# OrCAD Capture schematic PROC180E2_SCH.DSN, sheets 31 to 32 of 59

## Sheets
31 10. USB TYPE-C POWER: size C; title: USB TYPE-C POWER
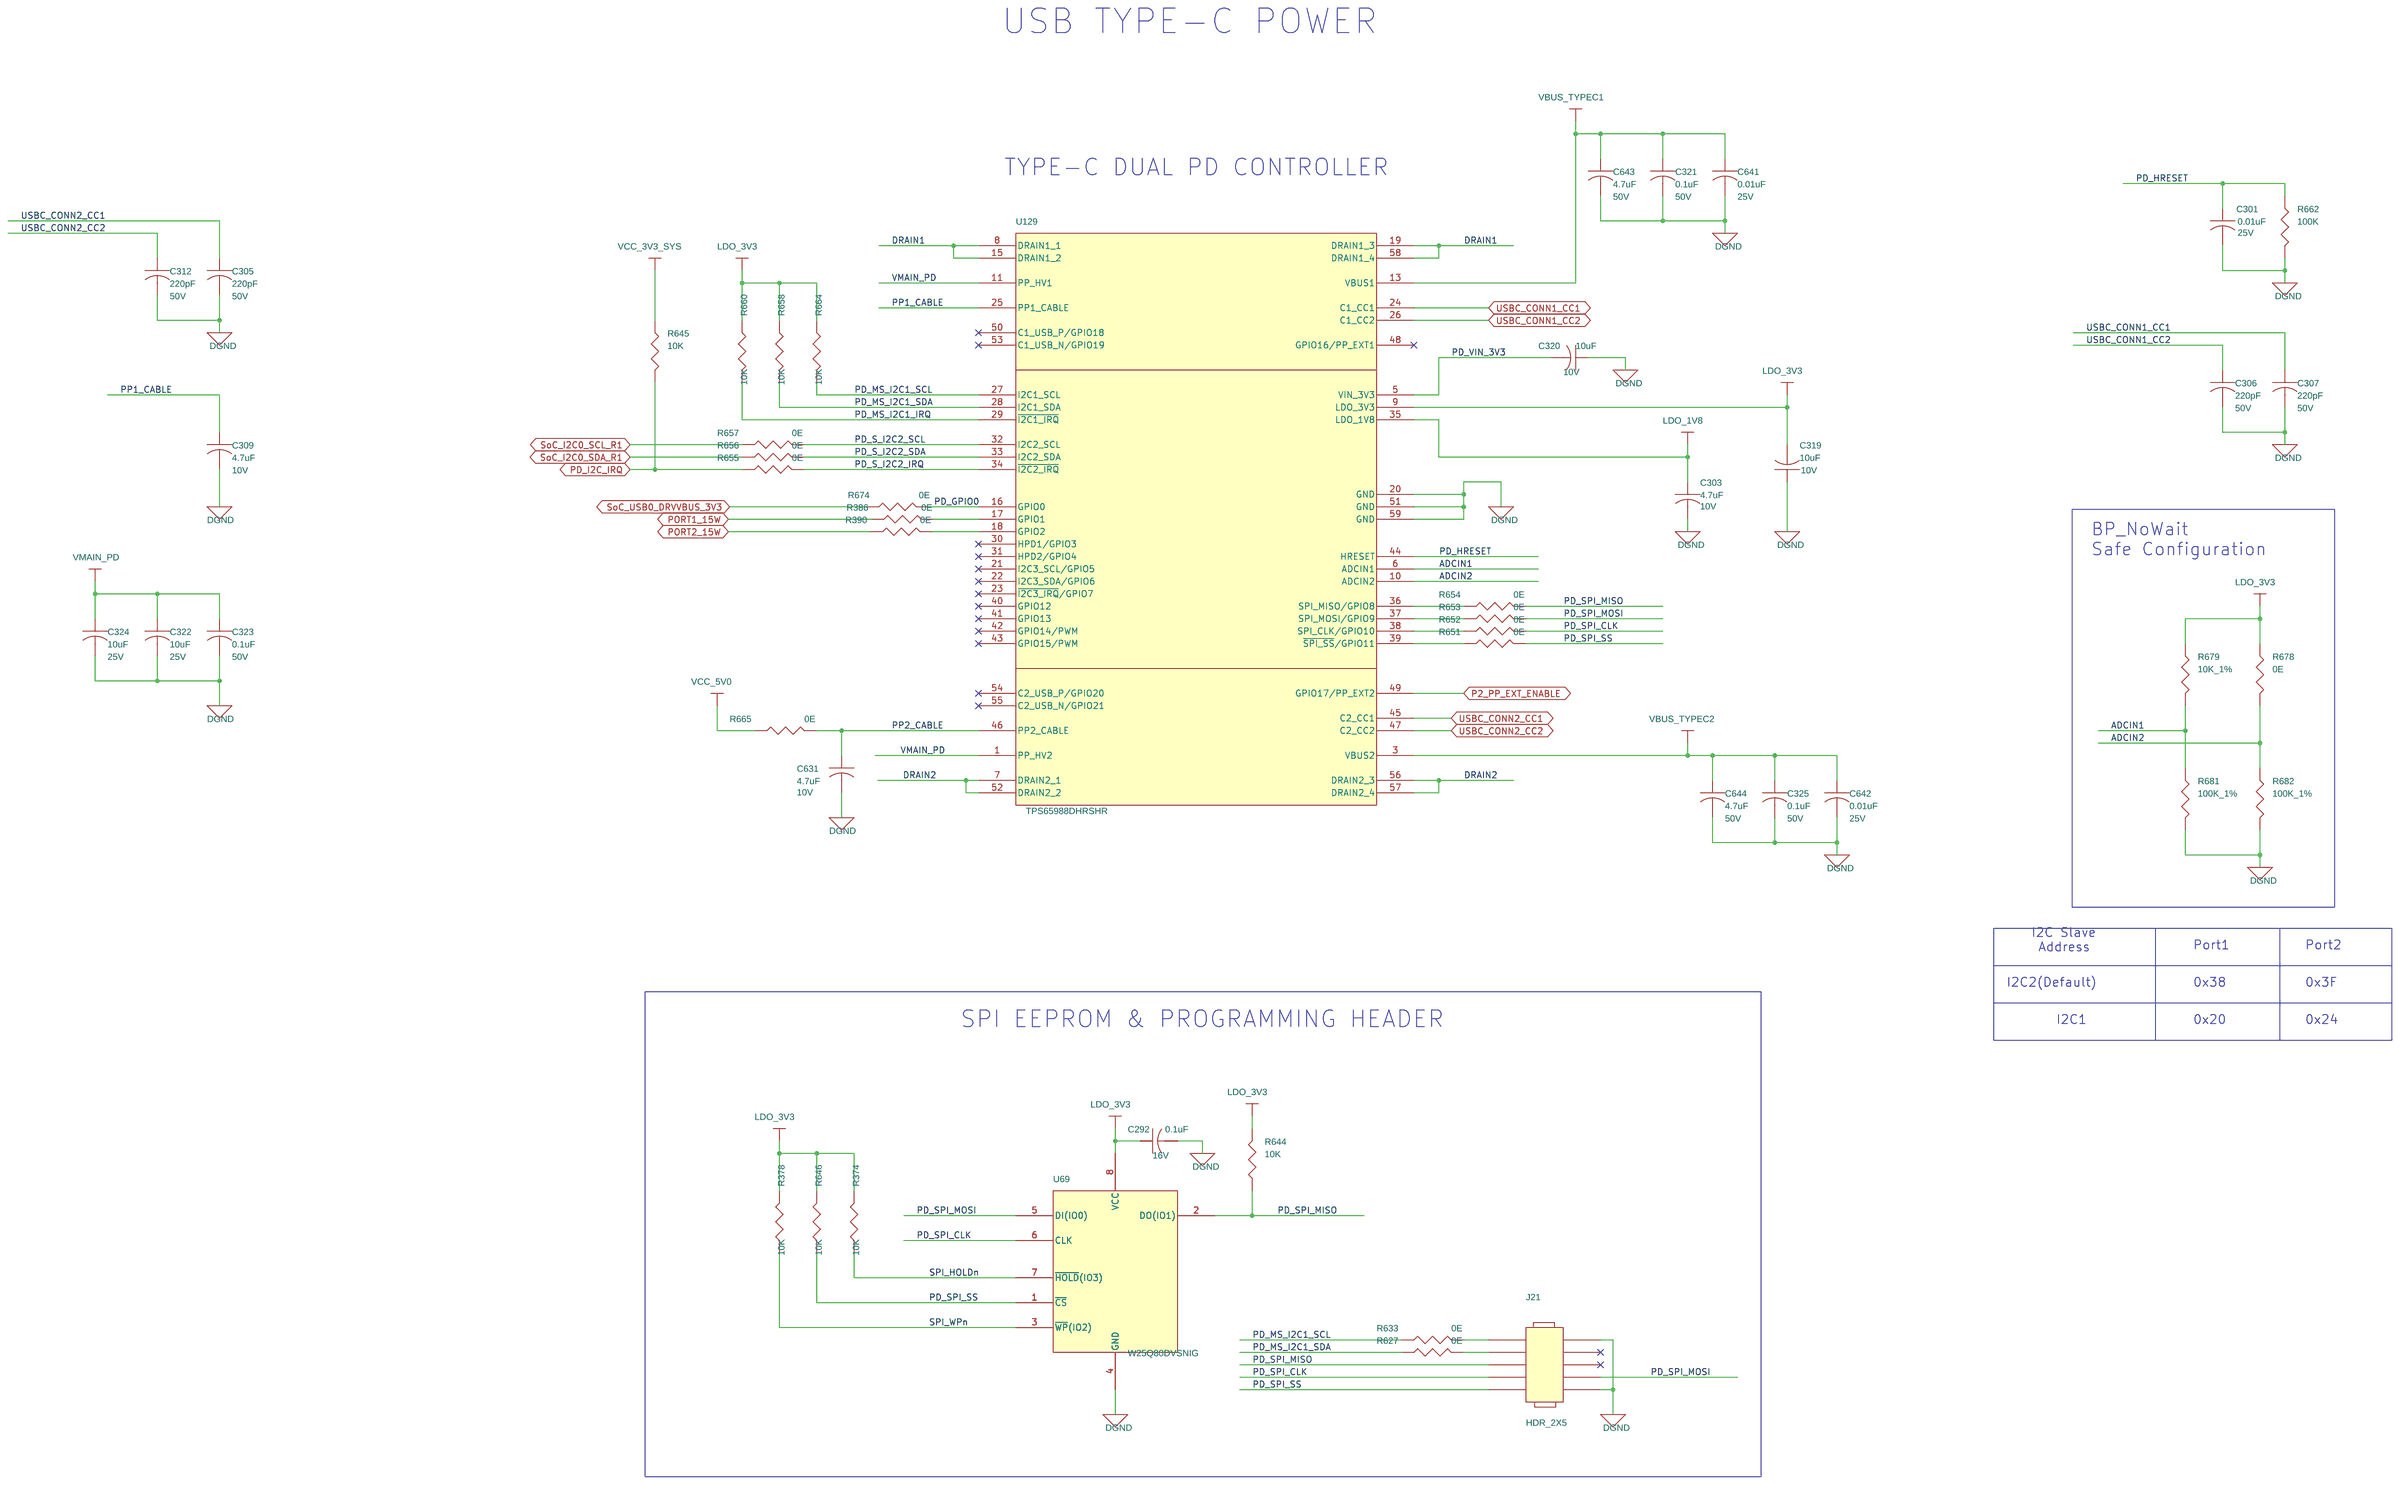
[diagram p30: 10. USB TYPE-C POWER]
32 12. PERIPHERAL POWER SUPPLY: size C; title: PERIPHERAL POWER SUPPLY
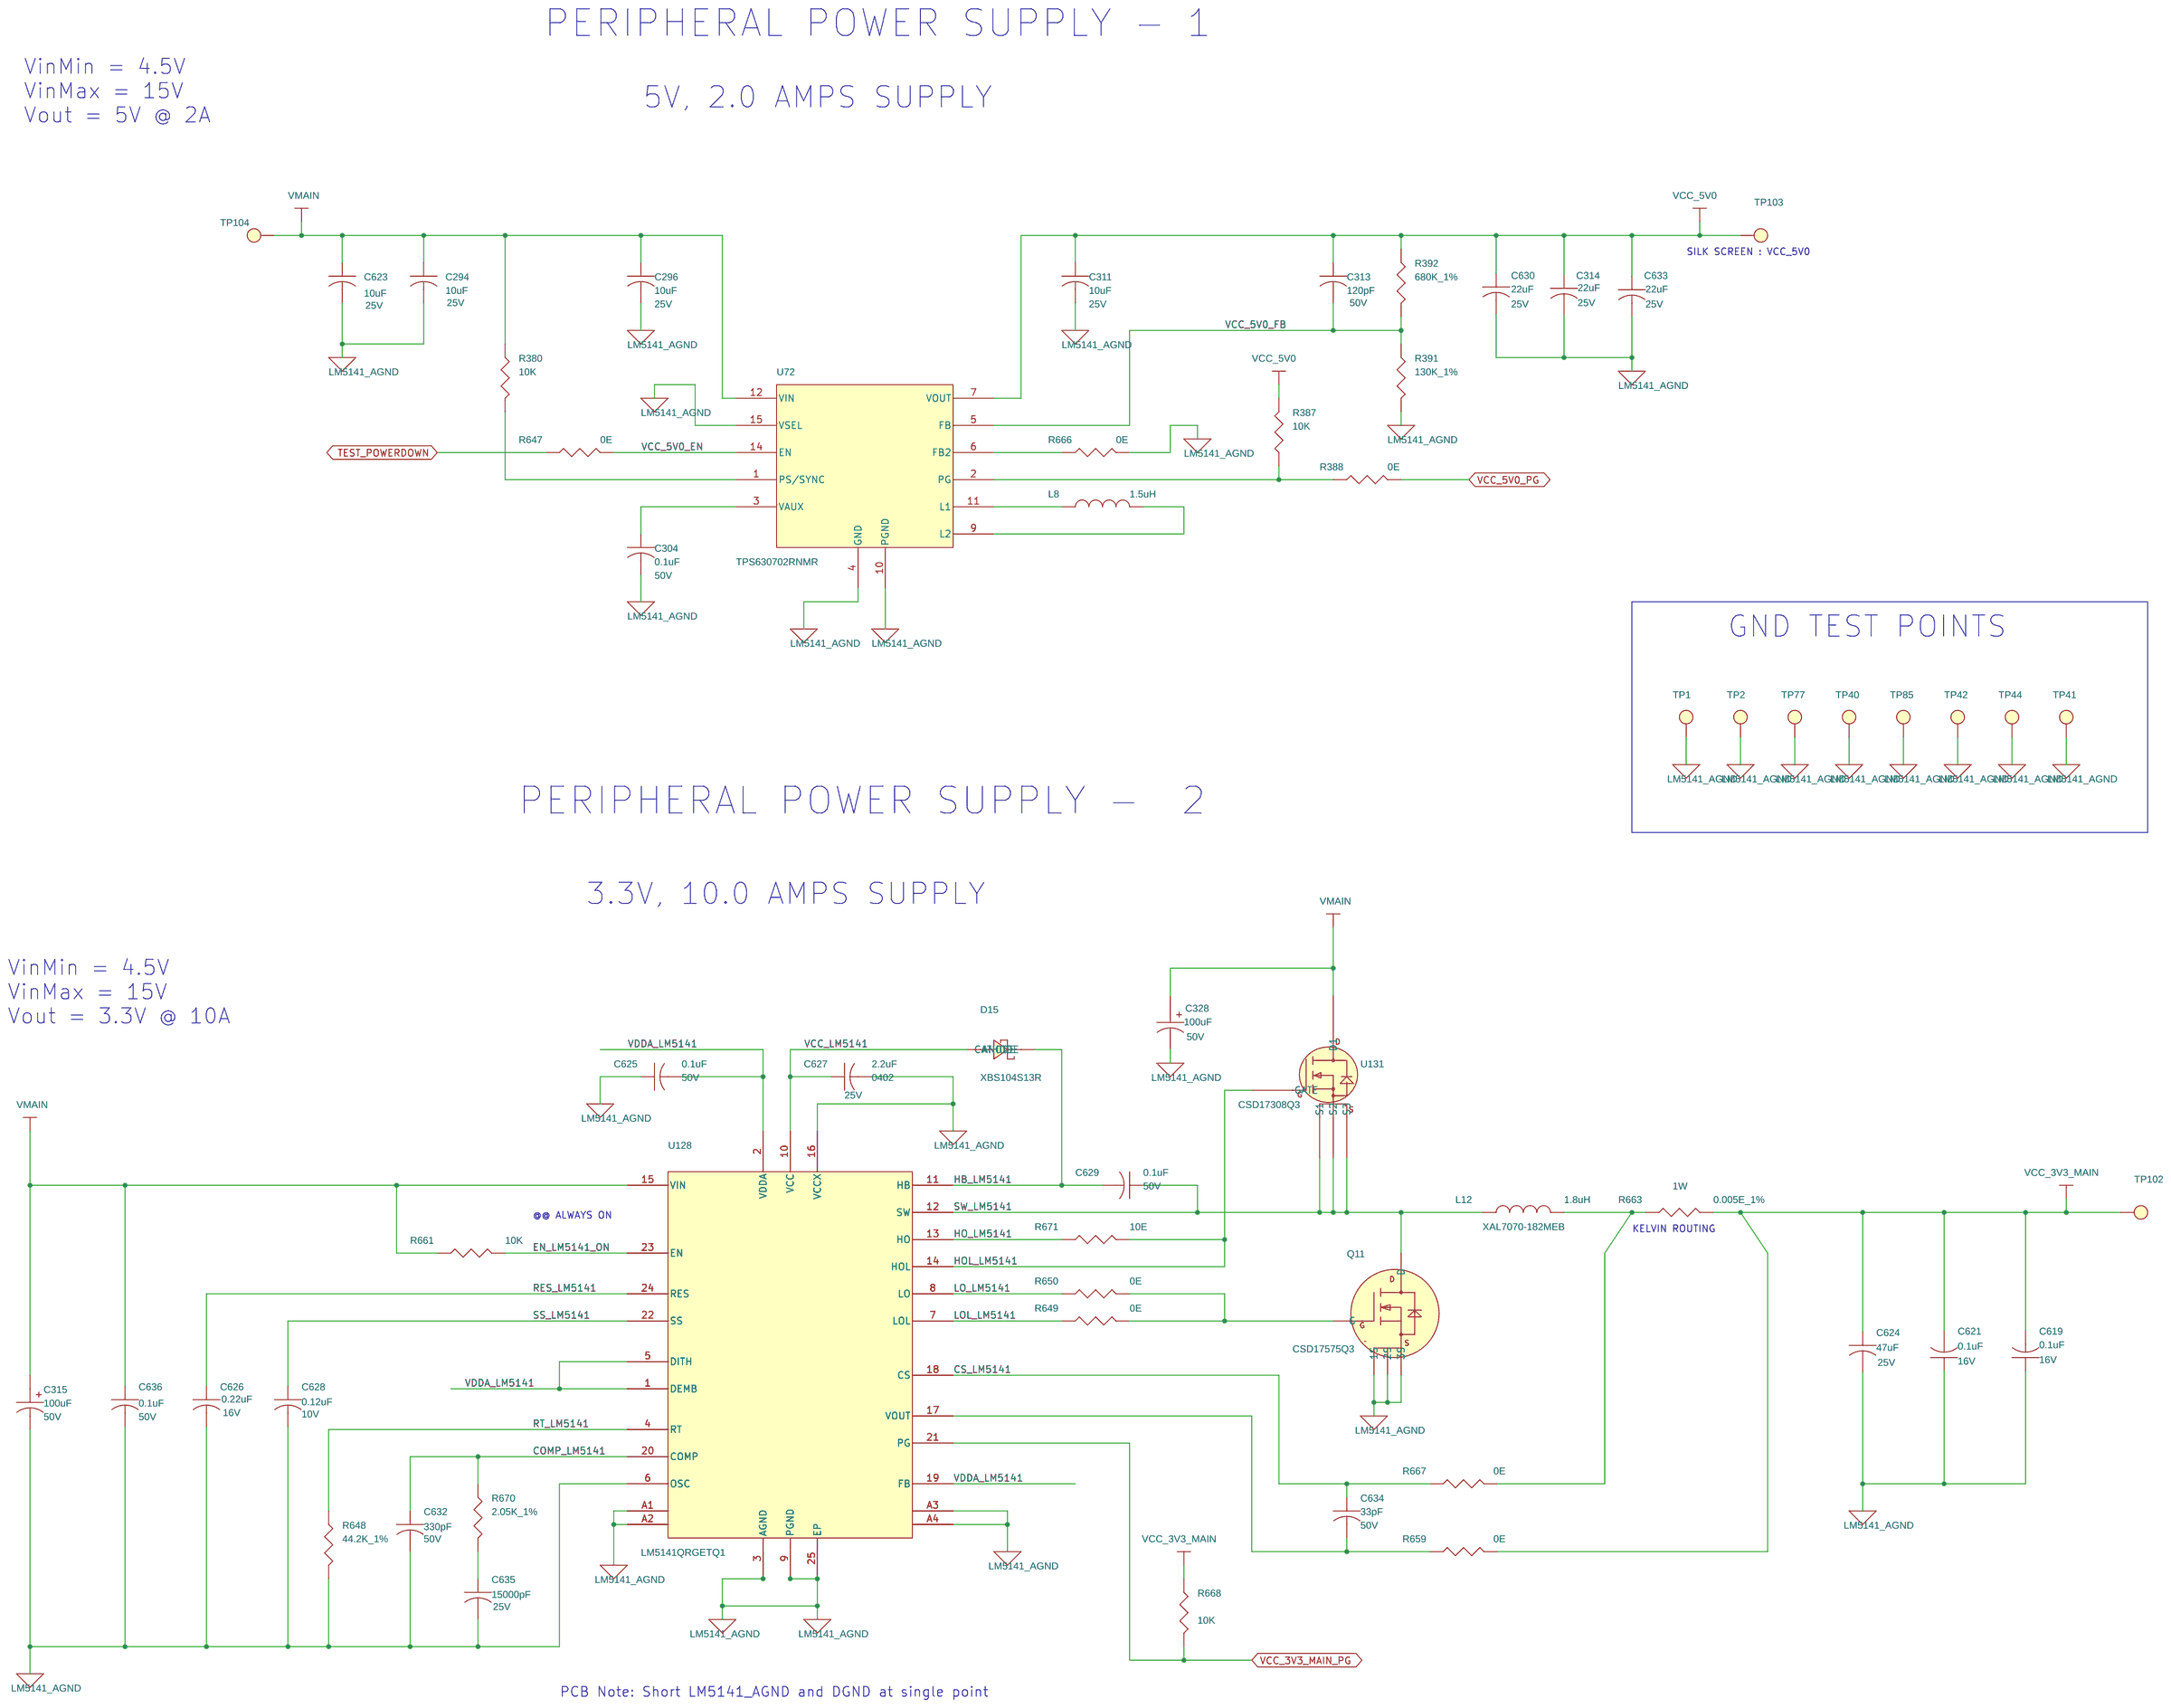
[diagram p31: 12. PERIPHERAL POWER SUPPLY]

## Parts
sheet 10. USB TYPE-C POWER
C292  0.1uF  [CAP0201_0-5]
C301  0.01uF  [CAP0201_0-5]
C303  4.7uF  [CAP0402_0-75]
C305  220pF  [CAP0402_0-75]
C306  220pF  [CAP0402_0-75]
C307  220pF  [CAP0402_0-75]
C309  4.7uF  [CAP0402_0-75]
C312  220pF  [CAP0402_0-75]
C319  10uF  [CAP0402_0-75]
C320  10uF  [CAP0402_0-75]
C321  0.1uF  [CAP0402_0-75]
C322  10uF  [CAP0603_1]
C323  0.1uF  [CAP0402_0-75]
C324  10uF  [CAP0603_1]
C325  0.1uF  [CAP0402_0-75]
C631  4.7uF  [CAP0402_0-75]
C641  0.01uF  [CAP0201_0-5]
C642  0.01uF  [CAP0201_0-5]
C643  4.7uF  [CAP0805_1-5]
C644  4.7uF  [CAP0805_1-5]
J21  HDR_2X5  [HDR_2X5_PEC05DAAN_S_T_8-6]
R374  10K  [RES0201_0-5]
R378  10K  [RES0201_0-5]
R386  0E  [RES0201_0-5]
R390  0E  [RES0201_0-5]
R627  0E  [RES0201_0-5]
R633  0E  [RES0201_0-5]
R644  10K  [RES0201_0-5]
R645  10K  [RES0201_0-5]
R646  10K  [RES0201_0-5]
R651  0E  [RES0201_0-5]
R652  0E  [RES0201_0-5]
R653  0E  [RES0201_0-5]
R654  0E  [RES0201_0-5]
R655  0E  [RES0201_0-5]
R656  0E  [RES0201_0-5]
R657  0E  [RES0201_0-5]
R658  10K  [RES0201_0-5]
R660  10K  [RES0201_0-5]
R662  100K  [RES0201_0-5]
R664  10K  [RES0201_0-5]
R665  0E  [RES0402_0-5]
R674  0E  [RES0201_0-5]
R678  0E  [RES0201_0-5]
R679  10K_1%  [RES0201_0-5]
R681  100K_1%  [RES0402_0-5]
R682  100K_1%  [RES0402_0-5]
U69  W25Q80DVSNIG  [SOIC8_1-8]
U129  TPS65988DHRSHR  [VQFN56_TPS65987D_280X280_1]
sheet 12. PERIPHERAL POWER SUPPLY
C294  10uF  [CAP0805_1-5]
C296  10uF  [CAP0603_1]
C304  0.1uF  [CAP0402_0-75]
C311  10uF  [CAP0603_1]
C313  120pF  [CAP0201_0-5]
C314  22uF  [CAP0805_1-5]
C315  100uF  [CAPAE_FCASE_10-5]
C328  100uF  [CAPAE_FCASE_10-5]
C619  0.1uF  [CAP0201_0-5]
C621  0.1uF  [CAP0201_0-5]
C623  10uF  [CAP0805_1-5]
C624  47uF  [CAP1206_2]
C625  0.1uF  [CAP0402_0-75]
C626  0.22uF  [CAP0402_0-75]
C627  2.2uF  [CAP0402_0-75]
C628  0.12uF  [CAP0603_1]
C629  0.1uF  [CAP0402_0-75]
C630  22uF  [CAP0805_1-5]
C632  330pF  [CAP0402_0-75]
C633  22uF  [CAP0805_1-5]
C634  33pF  [CAP0201_0-5]
C635  15000pF  [CAP0402_0-75]
C636  0.1uF  [CAP0402_0-75]
D15  XBS104S13R  [DIO_SOD323_1]
L8  1.5uH  [IND_XFL4020_170X170_SMD_2-1]
L12  1.8uH  [IND_XAL7070_300X310_SMD_7]
Q11  CSD17575Q3  [VSON8_CSD173_130X130_1-1]
R380  10K  [RES0201_0-5]
R387  10K  [RES0201_0-5]
R388  0E  [RES0201_0-5]
R391  130K_1%  [RES0402_0-5]
R392  680K_1%  [RES0402_0-5]
R647  0E  [RES0201_0-5]
R648  44.2K_1%  [RES0402_0-5]
R649  0E  [RES0402_0-5]
R650  0E  [RES0402_0-5]
R659  0E  [RES0201_0-5]
R661  10K  [RES0402_0-5]
R663  0.005E_1%  [RES1206_1]
R666  0E  [RES0201_0-5]
R667  0E  [RES0201_0-5]
R668  10K  [RES0402_0-5]
R670  2.05K_1%  [RES0402_0-5]
R671  10E  [RES0402_0-5]
TP1  THRU HOLE  [TP_40X65]
TP2  THRU HOLE  [TP_40X65]
TP40  THRU HOLE  [TP_40X65]
TP41  TP40_SMD  [TP40_SMD]
TP42  TP40_SMD  [TP40_SMD]
TP44  TP40_SMD  [TP40_SMD]
TP77  THRU HOLE  [TP_40X65]
TP85  THRU HOLE  [TP_40X65]
TP102  TP20_SMD  [TP20_SMD]
TP103  TP20_SMD  [TP20_SMD]
TP104  TP20_SMD  [TP20_SMD]
U72  TPS630702RNMR  [VQFNHR15_TPS630701_100X120_1]
U128  LM5141QRGETQ1  [VQFN24_LM5141_160X160_1]
U131  CSD17308Q3  [VSON8_CSD173_130X130]

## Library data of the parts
C292 = CAP: CAP CERAMIC 0.1uF 16V 10% X7S AUTO 0201; Chkd/date: MANIRAJA/110321; Crtd /date: ALVY/110321; Custom_Duty: 15%; Customs_HS_Code: 85322990; Distributor_name: DIGIKEY; Distributor_part_number: 490-GRT033C71C104KE01DTR-ND; Footprint Path: Y:\MIS_DATABASE\Library\ALTIUM_TOOL\PCB_FOOTPRINTS\Altium_Footprint_Lib.PcbLib; Height: 0.33MM; Library Path: Y:\MIS_DATABASE\Library\ALTIUM_TOOL\SCHEMATICS_PARTS\MS_DISCRETE_Library.schlib; Mfr_name: MURATA; Mfr_part_number: GRT033C71C104KE01D; Mistral Part No: 120021030007-R; Package: 0201; Part_type: CAPACITORS\CERAMIC; Project: J7ES_SK_BRD; RoHS: RoHS; Temperature: -55°C+125°C; Tolerance: 10%; Voltage: 16V; Wattage: NA; Weight: 330mg; Datasheet: Y:\MIS_DATABASE\DATASHEETS\CAPACITORS\GRT033C71C104KE01.PDF
C301 C641 C642 = CAP: CAP CERAMIC 0.01uF 25V 10% X5R AUTO 0201; Chkd/date: MANIRAJA/311221; Crtd /date: ALVY/301221; Custom_Duty: 15%; Customs_HS_Code: 85322990; Distributor_name: MOUSER; Distributor_part_number: 81-GRT033R61E103KE1D; Footprint Path: Y:\MIS_DATABASE\Library\ALTIUM_TOOL\PCB_FOOTPRINTS\Altium_Footprint_Lib.PcbLib; Height: 0.33MM; Library Path: Y:\MIS_DATABASE\Library\ALTIUM_TOOL\SCHEMATICS_PARTS\MS_DISCRETE_Library.schlib; Mfr_name: MURATA; Mfr_part_number: GRT033R61E103KE01D; Mistral Part No: 120021120019-R; Package: 0201; Part_type: CAPACITORS\CERAMIC; Project: AM62Q_SKEVM_BRD; RoHS: RoHS; Temperature: -55°C+85°C; Tolerance: 10%; Voltage: 25V; Wattage: NA; Weight: 0.33mg; Datasheet: Y:\MIS_DATABASE\DATASHEETS\CAPACITORS\GRT033R61E103KE01.PDF
C303 C309 C631 = CAP: CAP CERAMIC 4.7uF 10V 20% X5R AUTO 0402; Chkd/date: MANIRAJA/250221; Crtd /date: ALVY/240221; Custom_Duty: 15%; Customs_HS_Code: 85322990; Distributor_name: MOUSER; Distributor_part_number: 81-GRT155R61A475ME13; Footprint Path: Y:\MIS_DATABASE\Library\ALTIUM_TOOL\PCB_FOOTPRINTS\Altium_Footprint_Lib.PcbLib; Height: 0.65MM; Library Path: Y:\MIS_DATABASE\Library\ALTIUM_TOOL\SCHEMATICS_PARTS\MS_DISCRETE_Library.schlib; Mfr_name: MURATA; Mfr_part_number: GRT155R61A475ME13D; Mistral Part No: 120021020032-R; Package: 0402; Part_type: CAPACITORS\CERAMIC; Project: TI_DRA821 SK EVM BRD; RoHS: RoHS; Temperature: -55°C+85°C; Tolerance: 20%; Voltage: 10V; Wattage: NA; Weight: 1.5mg; Datasheet: Y:\MIS_DATABASE\DATASHEETS\CAPACITORS\GRT155R61A475ME13.PDF
C305-C307 C312 = CAP: CAP CERAMIC 220pF 50V 5% C0G(NP0) AUTO 0402; Chkd/date: PRADEEP/130623; Crtd /date: PRADEEP/130623; Custom_Duty: 15%; Customs_HS_Code: 85322990; Distributor_name: NA; Distributor_part_number: NA; Footprint Path: Y:\MIS_DATABASE\Library\ALTIUM_TOOL\PCB_FOOTPRINTS\Altium_Footprint_Lib.PcbLib; Height: 0.55MM; Library Path: Y:\MIS_DATABASE\Library\ALTIUM_TOOL\SCHEMATICS_PARTS\MS_DISCRETE_Library.schlib; Mfr_name: MURATA; Mfr_part_number: GRT1555C1H221JA02; Mistral Part No: 120022060024-R; Package: 0402; Part_type: CAPACITORS\CERAMIC; Project: AM62P_SK; RoHS: RoHS; Temperature: -55°C+125°C; Tolerance: 5%; Voltage: 50V; Wattage: NA; Weight: 3.1mg; Datasheet: Y:\MIS_DATABASE\DATASHEETS\CAPACITORS\GRT1555C1H221JA02.PDF
C319 C320 = CAP: CAP CERAMIC 10uF 10V 20% X5R 0402; Chkd/date: PRADEEP/130623; Crtd /date: PRADEEP/130623; Custom_Duty: 15%; Customs_HS_Code: 85322990; Distributor_name: NA; Distributor_part_number: NA; Footprint Path: Y:\MIS_DATABASE\Library\ALTIUM_TOOL\PCB_FOOTPRINTS\Altium_Footprint_Lib.PcbLib; Height: 0.55MM; Library Path: Y:\MIS_DATABASE\Library\ALTIUM_TOOL\SCHEMATICS_PARTS\MS_DISCRETE_Library.schlib; Mfr_name: MURATA; Mfr_part_number: GRM155R61A106ME18; Mistral Part No: 120022060018-R; Package: 0402; Part_type: CAPACITORS\CERAMIC; Project: AM62P_SK; RoHS: RoHS; Temperature: -55°C+85°C; Tolerance: 20%; Voltage: 10V; Wattage: NA; Weight: 6mg; Datasheet: Y:\MIS_DATABASE\DATASHEETS\CAPACITORS\MURATA-GXX-SER_NOV17.PDF
C304 C321 C323 C325 C625 C629 C636 = CAP: CAP CERAMIC 0.1uF 50V 10% X7R AUTO 0402; Chkd/date: MANIRAJA/250221; Crtd /date: ALVY/240221; Custom_Duty: 15%; Customs_HS_Code: 85322990; Distributor_name: MOUSER; Distributor_part_number: 81-GRT155R71H104KE1D; Footprint Path: Y:\MIS_DATABASE\Library\ALTIUM_TOOL\PCB_FOOTPRINTS\Altium_Footprint_Lib.PcbLib; Height: 0.55MM; Library Path: Y:\MIS_DATABASE\Library\ALTIUM_TOOL\SCHEMATICS_PARTS\MS_DISCRETE_Library.schlib; Mfr_name: MURATA; Mfr_part_number: GRT155R71H104KE01D; Mistral Part No: 120019030005-R; Package: 0402; Part_type: CAPACITORS\CERAMIC; Project: TI_DRA821 SK EVM BRD; RoHS: RoHS; Temperature: -55°C+125°C; Tolerance: 10%; Voltage: 50V; Wattage: NA; Weight: NA; Datasheet: Y:\MIS_DATABASE\DATASHEETS\CAPACITORS\GRT155R71H104KE01.PDF
C296 C311 C322 C324 = CAP: CAP CERAMIC 10uF 25V 20% X5R AUTO 0603; Chkd/date: PRADEEP/130623; Crtd /date: PRADEEP/130623; Custom_Duty: 15%; Customs_HS_Code: 85322990; Distributor_name: NA; Distributor_part_number: NA; Footprint Path: Y:\MIS_DATABASE\Library\ALTIUM_TOOL\PCB_FOOTPRINTS\Altium_Footprint_Lib.PcbLib; Height: 1.00MM; Library Path: Y:\MIS_DATABASE\Library\ALTIUM_TOOL\SCHEMATICS_PARTS\MS_DISCRETE_Library.schlib; Mfr_name: MURATA; Mfr_part_number: GRT188R61E106ME13; Mistral Part No: 120022060023-R; Package: 0603; Part_type: CAPACITORS\CERAMIC; Project: AM62P_SK; RoHS: RoHS; Temperature: -55°C+85°C; Tolerance: 20%; Voltage: 25V; Wattage: NA; Weight: 2mg; Datasheet: Y:\MIS_DATABASE\DATASHEETS\CAPACITORS\GRT188R61E106ME13.PDF
C643 C644 = CAP: CAP CERAMIC 4.7uF 50V 10% X5R 0805; Chkd/date: VASANTHA/281216; Crtd /date: BAVISH/290711; Custom_Duty: 15%; Customs_HS_Code: 85322990; Distributor_name: DIGIKEY; Distributor_part_number: 445-5980-1-ND; Footprint Path: Y:\MIS_DATABASE\Library\ALTIUM_TOOL\PCB_FOOTPRINTS\Altium_Footprint_Lib.PcbLib; Height: 1.45MM; Library Path: Y:\MIS_DATABASE\Library\ALTIUM_TOOL\SCHEMATICS_PARTS\MS_DISCRETE_Library.schlib; Mfr_name: TDK CORPORATION; Mfr_part_number: C2012X5R1H475K; Mistral Part No: 120011070010-R; Package: 0805; Part_type: CAPACITORS\CERAMIC; Project: OMAPL1_PEC20; RoHS: RoHS; Temperature: -55°C+85°C; Tolerance: 10%; Voltage: 50V; Wattage: NA; Weight: 5.5mg; Datasheet: Y:\MIS_DATABASE\DATASHEETS\CAPACITORS\TDK_C-SERIES.PDF
J21 = HEADER_5X2: CON HDR 2X5 2.54MM PITCH ST TH; Chkd/date: MANIRAJA/060821; Crtd /date: ALVY/060821; Custom_Duty: 24%; Customs_HS_Code: 85369090; Distributor_name: DIGIKEY; Distributor_part_number: S2012E-05-ND; Footprint Path: Y:\MIS_DATABASE\Library\ALTIUM_TOOL\PCB_FOOTPRINTS\Altium_Footprint_Lib.PcbLib; Height: 8.58MM; Library Path: Y:\MIS_DATABASE\Library\ALTIUM_TOOL\SCHEMATICS_PARTS\MS_CONNECTOR_Library.schlib; Mfr_name: SULLINS CONNECTOR; Mfr_part_number: PEC05DAAN; Mistral Part No: 150021080010-R; Package: THRU-HOLE; Part_type: CONNECTOR\HEADERS; Project: TI_AM335x SK_BRD; RoHS: RoHS; Temperature: -65°C+125°C; Tolerance: NA; Voltage: NA; Wattage: NA; Weight: NA; Datasheet: Y:\MIS_DATABASE\DATASHEETS\CONNECTORS\XXCXXDXXN.PDF
R374 R378 R380 R387 R644-R646 R658 R660 R664 = RESISTOR: RES 10K 1/20W 5% 0201; Chkd/date: MANIRAJA/050517; Crtd /date: MANIRAJA/050517; Custom_Duty: 15%; Customs_HS_Code: 85332119; Distributor_name: DIGIKEY; Distributor_part_number: 311-10KNCT-ND; Footprint Path: Y:\MIS_DATABASE\Library\ALTIUM_TOOL\PCB_FOOTPRINTS\Altium_Footprint_Lib.PcbLib; Height: 0.26MM; Library Path: Y:\MIS_DATABASE\Library\ALTIUM_TOOL\SCHEMATICS_PARTS\MS_DISCRETE_Library.schlib; Mfr_name: YAGEO AMERICA; Mfr_part_number: RC0201JR-0710KL; Mistral Part No: 110010070051-R; Package: 0201; Part_type: RESISTORS\FIXED; Project: GOLDEN-I LITE; RoHS: RoHS; Temperature: -55°C+125°C; Tolerance: 5%; Voltage: NA; Wattage: 1/20W; Weight: 0.17mg; Datasheet: Y:\MIS_DATABASE\DATASHEETS\RESISTORS\RCXXXXL-SER_MAR18.PDF
R386 R388 R390 R627 R633 R647 R651-R657 R659 R666 R667 R674 = RESISTOR: RES 0E 1/20W 5% 0201; Chkd/date: NAVEED/301214; Crtd /date: MUDDU/120710; Custom_Duty: 15%; Customs_HS_Code: 85332119; Distributor_name: DIGIKEY; Distributor_part_number: 311-0.0NCT-ND; Footprint Path: Y:\MIS_DATABASE\Library\ALTIUM_TOOL\PCB_FOOTPRINTS\Altium_Footprint_Lib.PcbLib; Height: 0.26MM; Library Path: Y:\MIS_DATABASE\Library\ALTIUM_TOOL\SCHEMATICS_PARTS\MS_DISCRETE_Library.schlib; Mfr_name: YAGEO AMERICA; Mfr_part_number: RC0201JR-070RL; Mistral Part No: 110010070067-R; Package: 0201; Part_type: RESISTORS\FIXED; Project: PB_BUGBASE; RoHS: RoHS; Temperature: -55°C+125°C; Tolerance: 5%; Voltage: NA; Wattage: 1/20W; Weight: 0.17mg; Datasheet: Y:\MIS_DATABASE\DATASHEETS\RESISTORS\RCXXXXL-SER_MAR18.PDF
R662 = RESISTOR: RES 100K 1/20W 5% 0201; Chkd/date: MANIRAJA/050517; Crtd /date: MANIRAJA/050517; Custom_Duty: 15%; Customs_HS_Code: 85332119; Distributor_name: DIGIKEY; Distributor_part_number: 311-100KNCT-ND; Footprint Path: Y:\MIS_DATABASE\Library\ALTIUM_TOOL\PCB_FOOTPRINTS\Altium_Footprint_Lib.PcbLib; Height: 0.26MM; Library Path: Y:\MIS_DATABASE\Library\ALTIUM_TOOL\SCHEMATICS_PARTS\MS_DISCRETE_Library.schlib; Mfr_name: YAGEO AMERICA; Mfr_part_number: RC0201JR-07100KL; Mistral Part No: 110009030176-R; Package: 0201; Part_type: RESISTORS\FIXED; Project: GOLDEN-I LITE; RoHS: RoHS; Temperature: -55°C+125°C; Tolerance: 5%; Voltage: NA; Wattage: 1/20W; Weight: 0.17mg; Datasheet: Y:\MIS_DATABASE\DATASHEETS\RESISTORS\RCXXXXL-SER_MAR18.PDF
R665 = RESISTOR: RES 0E 1/10W JUMPER 0402; Chkd/date: VASANTHA/061216; Crtd /date: NAVEED/201014; Custom_Duty: 15%; Customs_HS_Code: 85332119; Distributor_name: DIGIKEY; Distributor_part_number: P0.0JCT-ND; Footprint Path: Y:\MIS_DATABASE\Library\ALTIUM_TOOL\PCB_FOOTPRINTS\Altium_Footprint_Lib.PcbLib; Height: 0.40MM; IBISSP_MODLES: VALUE REPEATING 2 TIME; Library Path: Y:\MIS_DATABASE\Library\ALTIUM_TOOL\SCHEMATICS_PARTS\MS_DISCRETE_Library.schlib; Mfr_name: PANASONIC-ECG; Mfr_part_number: ERJ-2GE0R00X; Mistral Part No: 110018030052-R; Package: 0402; Part_type: RESISTORS\FIXED; Project: AEGIS POM; RoHS: RoHS; Temperature: -55°C+155°C; Tolerance: NA; Voltage: NA; Wattage: 1/10W; Weight: 0.8mg; Datasheet: Y:\MIS_DATABASE\DATASHEETS\RESISTORS\PAN-ERJSER_NOV17.PDF
R678 = RESISTOR: RES 0E 1/20W JUMPER 0201; Chkd/date: VASANTHA/061216; Crtd /date: MAZHAR/040505; Custom_Duty: 15%; Customs_HS_Code: 85332119; Distributor_name: DIGIKEY; Distributor_part_number: P0.0AGCT-ND; Footprint Path: Y:\MIS_DATABASE\Library\ALTIUM_TOOL\PCB_FOOTPRINTS\Altium_Footprint_Lib.PcbLib; Height: 0.26MM; Library Path: Y:\MIS_DATABASE\Library\ALTIUM_TOOL\SCHEMATICS_PARTS\MS_DISCRETE_Library.schlib; Mfr_name: PANASONIC-ECG; Mfr_part_number: ERJ-1GE0R00C; Mistral Part No: 110009030078-R; Package: 0201; Part_type: RESISTORS\FIXED; Project: HS100RD; RoHS: RoHS; Temperature: -55°C+125°C; Tolerance: NA; Voltage: NA; Wattage: 1/20W; Weight: 0.15mg; Datasheet: Y:\MIS_DATABASE\DATASHEETS\RESISTORS\PAN-ERJXGE-FEB06.PDF
R679 = RESISTOR: RES 10K 1/20W 1% 0201; Chkd/date: VASANTHA/270117; Crtd /date: MANIRAJA/270117; Custom_Duty: 15%; Customs_HS_Code: 85332119; Distributor_name: DIGIKEY; Distributor_part_number: 311-10.0KMCT-ND; Footprint Path: Y:\MIS_DATABASE\Library\ALTIUM_TOOL\PCB_FOOTPRINTS\Altium_Footprint_Lib.PcbLib; Height: 0.26MM; Library Path: Y:\MIS_DATABASE\Library\ALTIUM_TOOL\SCHEMATICS_PARTS\MS_DISCRETE_Library.schlib; Mfr_name: YAGEO AMERICA; Mfr_part_number: RC0201FR-0710KL; Mistral Part No: 110011040018-R; Package: 0201; Part_type: RESISTORS\FIXED; Project: GOLDEN-I LITE; RoHS: RoHS; Temperature: -55°C+125°C; Tolerance: 1%; Voltage: NA; Wattage: 1/20W; Weight: 0.17mg; Datasheet: Y:\MIS_DATABASE\DATASHEETS\RESISTORS\RCXXXXL-SER_MAR18.PDF
R681 R682 = RESISTOR: RES 100K 1/10W 1% 0402; Chkd/date: VASANTHA/201216; Crtd /date: MAZHAR/130306; Custom_Duty: 15%; Customs_HS_Code: 85332119; Distributor_name: DIGIKEY; Distributor_part_number: P100KLCT-ND; Footprint Path: Y:\MIS_DATABASE\Library\ALTIUM_TOOL\PCB_FOOTPRINTS\Altium_Footprint_Lib.PcbLib; Height: 0.40MM; Library Path: Y:\MIS_DATABASE\Library\ALTIUM_TOOL\SCHEMATICS_PARTS\MS_DISCRETE_Library.schlib; Mfr_name: PANASONIC-ECG; Mfr_part_number: ERJ-2RKF1003X; Mistral Part No: 110009030187-R; Package: 0402; Part_type: RESISTORS\FIXED; Project: J32; RoHS: RoHS; Temperature: -55°C+155°C; Tolerance: 1%; Voltage: NA; Wattage: 1/10W; Weight: 0.8mg; Datasheet: Y:\MIS_DATABASE\DATASHEETS\RESISTORS\PAN-ERJSER_NOV17.PDF
U69 = W25Q80BWSNIG_SOIC8: IC SERIAL FLASH MEMORY SOIC8; Chkd/date: VASANTHA/150217; Crtd /date: MANIRAJA/150217; Custom_Duty: 15%; Customs_HS_Code: 85423100; Distributor_name: DIGIKEY; Distributor_part_number: W25Q80DVSNIG CT-ND; Height: 1.75MM; Mfr_name: WINBOND; Mfr_part_number: W25Q80DVSNIG-TR; Mistral Part No: 141117020010-R; Package: SOIC8; Part_type: ICS\DIGITAL\MEMORY; Project: SD820_NANO_SOM; RoHS: RoHS; Temperature: -40°C+85°C; Tolerance: NA; Voltage: NA; Wattage: NA; Weight: NA; Datasheet: Y:\MIS_DATABASE\DATASHEETS\ICS\MEMORY\W25Q80DVSS.PDF
U129 = TPS65988DJ_VQFN56: IC 2-PORT USB TYPE-C AND USB PD CONTROLLER WITH INTEGRATED POWER SWITCH VQFN56; Chkd/date: MANIRAJA/290721; Crtd /date: ALVY/280721; Custom_Duty: 15%; Customs_HS_Code: 85423100; Distributor_name: DIGIKEY; Distributor_part_number: 296-52068-1-ND; Footprint Path: Y:\MIS_DATABASE\Library\ALTIUM_TOOL\PCB_FOOTPRINTS\Altium_Footprint_Lib.PcbLib; Height: 1.00MM; Library Path: Y:\MIS_DATABASE\Library\ALTIUM_TOOL\SCHEMATICS_PARTS\MS_MISCPOWER_Library.schlib; Mfr_name: TEXAS INSTRUMENTS; Mistral Part No: 142021070017-R; Package: VQFN56; Part_type: ICS\POWER\MANAGEMENT; Project: TI_AM62x_SKEVM; RoHS: RoHS; Temperature: -10°C+75°C; Tolerance: NA; Voltage: NA; Wattage: NA; Weight: 127.6mg; Datasheet: Y:\MIS_DATABASE\DATASHEETS\ICS\POWER\TPS65988DHRSHR.PDF
C294 C623 = CAP: CAP CERAMIC 10uF 25V 10% X7S 0805; Chkd/date: PRADEEP/130623; Crtd /date: PRADEEP/130623; Custom_Duty: 15%; Customs_HS_Code: 85322990; Distributor_name: DIGIKEY; Distributor_part_number: 490-GRT21BC71E106KE13LCT-ND; Footprint Path: Y:\MIS_DATABASE\Library\ALTIUM_TOOL\PCB_FOOTPRINTS\Altium_Footprint_Lib.PcbLib; Height: 1.45MM; Library Path: Y:\MIS_DATABASE\Library\ALTIUM_TOOL\SCHEMATICS_PARTS\MS_DISCRETE_Library.schlib; Mfr_name: MURATA; Mfr_part_number: GRT21BC71E106KE13L; Mistral Part No: 120022060025-R; Package: 0805; Part_type: CAPACITORS\CERAMIC; Project: AM62P_SK; RoHS: RoHS; Temperature: -55°C+125°C; Tolerance: 10%; Voltage: 25V; Wattage: NA; Weight: 5.5mg; Datasheet: Y:\MIS_DATABASE\DATASHEETS\CAPACITORS\GRT21BC71E106KE13L.PDF
C313 = CAP: CAP CERAMIC 120pF 50V 5% C0G(NP0) AUTO 0201; Chkd/date: MANIRAJA/311221; Crtd /date: ALVY/301221; Custom_Duty: 15%; Customs_HS_Code: 85322990; Distributor_name: MOUSER; Distributor_part_number: 81-GRT0335C1H121JA2D; Footprint Path: Y:\MIS_DATABASE\Library\ALTIUM_TOOL\PCB_FOOTPRINTS\Altium_Footprint_Lib.PcbLib; Height: 0.33MM; Library Path: Y:\MIS_DATABASE\Library\ALTIUM_TOOL\SCHEMATICS_PARTS\MS_DISCRETE_Library.schlib; Mfr_name: MURATA; Mfr_part_number: GRT0335C1H121JA02D; Mistral Part No: 120021120016-R; Package: 0201; Part_type: CAPACITORS\CERAMIC; Project: AM62Q_SKEVM_BRD; RoHS: RoHS; Temperature: -55°C+125°C; Tolerance: 5%; Voltage: 50V; Wattage: NA; Weight: 0.33mg; Datasheet: Y:\MIS_DATABASE\DATASHEETS\CAPACITORS\GRT0335C1H121JA02.PDF
C314 C630 C633 = CAP: CAP CERAMIC 22uF 25V 20% X5R AUTO 0805; Chkd/date: VASANTHA/080716; Crtd /date: VASANTHA/080716; Custom_Duty: 15%; Customs_HS_Code: 85322990; Distributor_name: DIGIKEY; Distributor_part_number: 490-12389-1-ND; Footprint Path: Y:\MIS_DATABASE\Library\ALTIUM_TOOL\PCB_FOOTPRINTS\Altium_Footprint_Lib.PcbLib; Height: 1.45MM; Library Path: Y:\MIS_DATABASE\Library\ALTIUM_TOOL\SCHEMATICS_PARTS\MS_DISCRETE_Library.schlib; Mfr_name: MURATA; Mfr_part_number: GRT21BR61E226ME13L; Mistral Part No: 120016070003-R; Package: 0805; Part_type: CAPACITORS\CERAMIC; Project: 10_SLOT_VPX_BP; RoHS: RoHS; Temperature: -55°C+85°C; Tolerance: 20%; Voltage: 25V; Wattage: NA; Weight: 5.5mg; Datasheet: Y:\MIS_DATABASE\DATASHEETS\CAPACITORS\GRT21BR60J476ME13L.PDF
C315 C328 = CAP_POL: CAP ELECTROLYTIC 100uF 50V 20% CASE_8383; Chkd/date: MANIRAJA/221021; Crtd /date: TAMILARASU/221021; Custom_Duty: 15%; Customs_HS_Code: 85322990; Distributor_name: DIGIKEY; Distributor_part_number: 3372-UT107M050HFKTATR-ND; Footprint Path: Y:\MIS_DATABASE\Library\ALTIUM_TOOL\PCB_FOOTPRINTS\Altium_Footprint_Lib.PcbLib; Footprint Ref: CAPAE_D8CASE_8; Height: 10.50MM; Library Path: Y:\MIS_DATABASE\Library\ALTIUM_TOOL\SCHEMATICS_PARTS\MS_DISCRETE_Library.schlib; Mfr_name: NEXTGEN; Mfr_part_number: UT107M050HFKTA; Mistral Part No: 120021100004-R; Package: CASE_8383; Part_type: CAPACITORS\ELECTROLYTIC; Project: TI_J7AEP_SK_BRD; RoHS: RoHS; Temperature: -55°C+105°C; Tolerance: 20%; Voltage: 50V; Wattage: NA; Weight: NA; Datasheet: Y:\MIS_DATABASE\DATASHEETS\CAPACITORS\UT107M050HFKTA.PDF
C619 C621 = CAP: CAP CERAMIC 0.1uF 16V 10% X7S AUTO 0201; Chkd/date: MANIRAJA/110321; Crtd /date: ALVY/110321; Custom_Duty: 15%; Customs_HS_Code: 85322990; Distributor_name: DIGIKEY; Distributor_part_number: 490-GRT033C71C104KE01DTR-ND; Height: 0.33MM; Mfr_name: MURATA; Mfr_part_number: GRT033C71C104KE01D; Mistral Part No: 120021030007-R; Package: 0201; Part_type: CAPACITORS\CERAMIC; Project: J7ES_SK_BRD; RoHS: RoHS; Temperature: -55°C+125°C; Tolerance: 10%; Voltage: 16V; Wattage: NA; Weight: 330mg; Datasheet: Y:\MIS_DATABASE\DATASHEETS\CAPACITORS\GRT033C71C104KE01.PDF
C624 = CAP: CAP CERAMIC 47uF 25V 20% X5R 1206; Chkd/date: VASANTHA/261214; Crtd /date: USMAN/160513; Custom_Duty: 15%; Customs_HS_Code: 85322990; Distributor_name: DIGIKEY; Distributor_part_number: 445-8047-1-ND; Footprint Path: Y:\MIS_DATABASE\Library\ALTIUM_TOOL\PCB_FOOTPRINTS\Altium_Footprint_Lib.PcbLib; Height: 1.80MM; Library Path: Y:\MIS_DATABASE\Library\ALTIUM_TOOL\SCHEMATICS_PARTS\MS_DISCRETE_Library.schlib; Mfr_name: TDK CORPORATION; Mfr_part_number: C3216X5R1E476M160AC; Mistral Part No: 120013050002-R; Package: 1206; Part_type: CAPACITORS\CERAMIC; Project: ERP; RoHS: RoHS; Temperature: -55°C+85°C; Tolerance: 20%; Voltage: 25V; Wattage: NA; Weight: 16.2mg; Datasheet: Y:\MIS_DATABASE\DATASHEETS\CAPACITORS\TDK_C-SER-JUL17.PDF
C626 = CAP: CAP CERAMIC 0.22uF 16V 10% X7R 0402; Chkd/date: MANIRAJA/210817; Crtd /date: MANIRAJA/210817; Custom_Duty: 15%; Customs_HS_Code: 85322990; Distributor_name: DIGIKEY; Distributor_part_number: 490-5418-1-ND; Footprint Path: Y:\MIS_DATABASE\Library\ALTIUM_TOOL\PCB_FOOTPRINTS\Altium_Footprint_Lib.PcbLib; Height: 0.55MM; Library Path: Y:\MIS_DATABASE\Library\ALTIUM_TOOL\SCHEMATICS_PARTS\MS_DISCRETE_Library.schlib; Mfr_name: MURATA; Mfr_part_number: GRM155R71C224KA12D; Mistral Part No: 120011100002-R; Package: 0402; Part_type: CAPACITORS\CERAMIC; Project: TI_RF_DC CARD; RoHS: RoHS; Temperature: -55°C+125°C; Tolerance: 10%; Voltage: 16V; Wattage: NA; Weight: 6mg; Datasheet: Y:\MIS_DATABASE\DATASHEETS\CAPACITORS\MURATA-GXX-SER_NOV17.PDF
C627 = CAP: CAP CERAMIC 2.2uF 25V 10% X5R AUTO 0402; Chkd/date: MANIRAJA/240920; Crtd /date: ALVY/240920; Custom_Duty: 15%; Customs_HS_Code: 85322990; Distributor_name: DIGIKEY; Distributor_part_number: 490-12267-1-ND; Footprint Path: Y:\MIS_DATABASE\Library\ALTIUM_TOOL\PCB_FOOTPRINTS\Altium_Footprint_Lib.PcbLib; Height: 0.70MM; Library Path: Y:\MIS_DATABASE\Library\ALTIUM_TOOL\SCHEMATICS_PARTS\MS_DISCRETE_Library.schlib; Mfr_name: MURATA; Mfr_part_number: GRT155R61E225KE13D; Mistral Part No: 120020090019-R; Package: 0402; Part_type: CAPACITORS\CERAMIC; Project: ECU_RO; RoHS: RoHS; Temperature: -55°C+85°C; Tolerance: 10%; Voltage: 25V; Wattage: NA; Weight: 0.65mg; Datasheet: Y:\MIS_DATABASE\DATASHEETS\CAPACITORS\GRT155R61E225KE13.PDF
C628 = CAP: CAP CERAMIC 0.12uF 10V 10% X7R 0603; Chkd/date: MANIRAJA/080519; Crtd /date: ALVY/080519; Custom_Duty: 15%; Customs_HS_Code: 85322990; Distributor_name: DIGIKEY; Distributor_part_number: 311-4056-1-ND; Footprint Path: Y:\MIS_DATABASE\Library\ALTIUM_TOOL\PCB_FOOTPRINTS\Altium_Footprint_Lib.PcbLib; Height: 0.90MM; Library Path: Y:\MIS_DATABASE\Library\ALTIUM_TOOL\SCHEMATICS_PARTS\MS_DISCRETE_Library.schlib; Mfr_name: YAGEO AMERICA; Mfr_part_number: CC0603KRX7R6BB124; Mistral Part No: 120019050003-R; Package: 0603; Part_type: CAPACITORS\CERAMIC; Project: BRUKER_SD820_COMMONDO; RoHS: RoHS; Temperature: -55°C+125°C; Tolerance: 10%; Voltage: 10V; Wattage: NA; Weight: 2mg; Datasheet: Y:\MIS_DATABASE\DATASHEETS\CAPACITORS\YACC-X7R.PDF
C632 = CAP: CAP CERAMIC 330pF 50V 5% C0G(NP0) AUTO 0402; Chkd/date: MANIRAJA/250221; Crtd /date: ALVY/240221; Custom_Duty: 15%; Customs_HS_Code: 85322990; Distributor_name: MOUSER; Distributor_part_number: 81-GRT1555C1H331JA2D; Footprint Path: Y:\MIS_DATABASE\Library\ALTIUM_TOOL\PCB_FOOTPRINTS\Altium_Footprint_Lib.PcbLib; Height: 0.55MM; Library Path: Y:\MIS_DATABASE\Library\ALTIUM_TOOL\SCHEMATICS_PARTS\MS_DISCRETE_Library.schlib; Mfr_name: MURATA; Mfr_part_number: GRT1555C1H331JA02D; Mistral Part No: 120019050019-R; Package: 0402; Part_type: CAPACITORS\CERAMIC; Project: TI_DRA821 SK EVM BRD; RoHS: RoHS; Temperature: -55°C+125°C; Tolerance: 5%; Voltage: 50V; Wattage: NA; Weight: 3.1mg; Datasheet: Y:\MIS_DATABASE\DATASHEETS\CAPACITORS\GRT1555C1H331JA02.PDF
C634 = CAP: CAP CERAMIC 33pF 50V 5% C0G(NP0) 0201; Chkd/date: NAVEED/270515; Crtd /date: NAVEED/270515; Custom_Duty: 15%; Customs_HS_Code: 85322990; Distributor_name: DIGIKEY; Distributor_part_number: 490-6126-1-ND; Footprint Path: Y:\MIS_DATABASE\Library\ALTIUM_TOOL\PCB_FOOTPRINTS\Altium_Footprint_Lib.PcbLib; Height: 0.33MM; Library Path: Y:\MIS_DATABASE\Library\ALTIUM_TOOL\SCHEMATICS_PARTS\MS_DISCRETE_Library.schlib; Mfr_name: MURATA; Mfr_part_number: GRM0335C1H330JA01D; Mistral Part No: 120015050010-R; Package: 0201; Part_type: CAPACITORS\CERAMIC; Project: DUET BOARD; RoHS: RoHS; Temperature: -55°C+125°C; Tolerance: 5%; Voltage: 50V; Wattage: NA; Weight: 0.33mg; Datasheet: Y:\MIS_DATABASE\DATASHEETS\CAPACITORS\MURATA-GXX-SER_NOV17.PDF
C635 = CAP: CAP CERAMIC 15000pF 25V 10% X7R 0402; Chkd/date: PRADEEP/080324; Crtd /date: TAMILARASU/080324; Custom_Duty: 15%; Customs_HS_Code: 85322990; Distributor_name: NA; Distributor_part_number: NA; Footprint Path: Y:\MIS_DATABASE\Library\ALTIUM_TOOL\PCB_FOOTPRINTS\Altium_Footprint_Lib.PcbLib; Height: 0.55MM; Library Path: Y:\MIS_DATABASE\Library\ALTIUM_TOOL\SCHEMATICS_PARTS\MS_DISCRETE_Library.schlib; Mfr_name: MURATA; Mfr_part_number: GRM155R71E153KA61; Mistral Part No: 120024030009-R; Package: 0402; Part_type: CAPACITORS\CERAMIC; Project: AM62D_EVM; RoHS: RoHS; Temperature: -55°C+125°C; Tolerance: 10%; Voltage: 25V; Wattage: NA; Weight: 6mg; Datasheet: Y:\MIS_DATABASE\DATASHEETS\CAPACITORS\GRM155R71E153KA61.PDF
D15 = DIODE_SCHOTTKY: DIODE SCHOTTKY 40V 1A SOD323A; Chkd/date: MANIRAJA/150218; Crtd /date: ALVY/150218; Custom_Duty: 24%; Customs_HS_Code: 85437099; Distributor_name: DIGIKEY; Distributor_part_number: 893-1188-1-ND; Footprint Path: Y:\MIS_DATABASE\Library\ALTIUM_TOOL\PCB_FOOTPRINTS\Altium_Footprint_Lib.PcbLib; Height: 1.00MM; Library Path: Y:\MIS_DATABASE\Library\ALTIUM_TOOL\SCHEMATICS_PARTS\MS_DISCRETE_Library.schlib; Mfr_name: TOREX; Mfr_part_number: XBS104S13R-G; Mistral Part No: 130018020038-R; Package: SOD323; Part_type: DIODE\SCHOTTKY; Project: TI_MAXIE_CPB; RoHS: RoHS; Temperature: NA; Tolerance: NA; Voltage: 40V; Wattage: NA; Weight: NA; Datasheet: Y:\MIS_DATABASE\DATASHEETS\DISCRETES\DIODES\XBS104S13R-G.PDF
L8 = INDUCTOR: IND POWER 1.5uH 9.1A 20% SMD; Chkd/date: MANIRAJA/101019; Crtd /date: MANIRAJA/101019; Custom_Duty: 24%; Customs_HS_Code: 85437099; Distributor_name: MOUSER; Distributor_part_number: 994-XFL4020-152MEB; Footprint Path: Y:\MIS_DATABASE\Library\ALTIUM_TOOL\PCB_FOOTPRINTS\Altium_Footprint_Lib.PcbLib; Height: 2.10MM; Library Path: Y:\MIS_DATABASE\Library\ALTIUM_TOOL\SCHEMATICS_PARTS\MS_DISCRETE_Library.schlib; Mfr_name: COIL CRAFT; Mfr_part_number: XFL4020-152MEB; Mistral Part No: 130019100011-R; Package: SMD; Project: NPOL_UAIS_CONTROLLER-CARD; RoHS: RoHS; Temperature: -40°C+125°C; Tolerance: 20%; Voltage: NA; Wattage: NA; Weight: 169mg; Datasheet: Y:\MIS_DATABASE\DATASHEETS\DISCRETES\INDUCTORS\XFL4020.PDF
L12 = INDUCTOR: IND POWER 1.8uH 21A 20% SMD; Chkd/date: ALVY/221019; Crtd /date: MANIRAJA/221019; Custom_Duty: 24%; Customs_HS_Code: 85437099; Distributor_name: MOUSER; Distributor_part_number: 994-XAL7070-182MEB; Footprint Path: Y:\MIS_DATABASE\Library\ALTIUM_TOOL\PCB_FOOTPRINTS\Altium_Footprint_Lib.PcbLib; Height: 7.00MM; Library Path: Y:\MIS_DATABASE\Library\ALTIUM_TOOL\SCHEMATICS_PARTS\MS_DISCRETE_Library.schlib; Mfr_name: COIL CRAFT; Mfr_part_number: XAL7070-182MEB; Mistral Part No: 130019100031-R; Package: SMD; Project: BEL_QDR_BRD; RoHS: RoHS; Temperature: -40°C+125°C; Tolerance: 20%; Voltage: NA; Wattage: NA; Weight: 2100mg; Datasheet: Y:\MIS_DATABASE\DATASHEETS\DISCRETES\INDUCTORS\XAL7070_JUN19.PDF
Q11 = MOSFET_CSD17301Q5A: IC MOSFET N-CHANNEL NEXFET 30V VSON-CLIP8; Chkd/date: MANIRAJA/180820; Crtd /date: ALVY/180820; Custom_Duty: 15%; Customs_HS_Code: 85423100; Distributor_name: DIGIKEY; Distributor_part_number: 296-39994-1-ND; Footprint Path: Y:\MIS_DATABASE\Library\ALTIUM_TOOL\PCB_FOOTPRINTS\Altium_Footprint_Lib.PcbLib; Height: 1.10MM; Library Path: Y:\MIS_DATABASE\Library\ALTIUM_TOOL\SCHEMATICS_PARTS\MS_MOSFET_Library.schlib; Mfr_name: TEXAS INSTRUMENTS; Mistral Part No: 142020080002-R; Package: VSON-CLIP8; Part_type: ICS\POWER\MOSFET; Project: ISSI TDA4VM; RoHS: RoHS; Temperature: -55°C+150°C; Tolerance: NA; Voltage: NA; Wattage: NA; Weight: 44.5mg; Datasheet: Y:\MIS_DATABASE\DATASHEETS\ICS\POWER\CSD17575Q3.PDF
R391 = RESISTOR: RES 130K 1/10W 1% 0402; Chkd/date: MAZHAR/150611; Crtd /date: BAVISH/020611; Custom_Duty: 15%; Customs_HS_Code: 85332119; Distributor_name: DIGIKEY; Distributor_part_number: P130KLCT-ND; Footprint Path: Y:\MIS_DATABASE\Library\ALTIUM_TOOL\PCB_FOOTPRINTS\Altium_Footprint_Lib.PcbLib; Height: 0.40MM; Library Path: Y:\MIS_DATABASE\Library\ALTIUM_TOOL\SCHEMATICS_PARTS\MS_DISCRETE_Library.schlib; Mfr_name: PANASONIC-ECG; Mfr_part_number: ERJ-2RKF1303X; Mistral Part No: 110011060012-R; Package: 0402; Part_type: RESISTORS\FIXED; Project: AM4515_EVM_LCD; RoHS: RoHS; Temperature: -55°C+155°C; Tolerance: 1%; Voltage: NA; Wattage: 1/10W; Weight: 0.8mg; Datasheet: Y:\MIS_DATABASE\DATASHEETS\RESISTORS\PAN-ERJSER_NOV17.PDF
R392 = RESISTOR: RES 680K 1/10W 1% 0402; Chkd/date: SUHAS/200411; Crtd /date: MAZHAR/180411; Custom_Duty: 15%; Customs_HS_Code: 85332119; Distributor_name: DIGIKEY; Distributor_part_number: P680KLCT-ND; Footprint Path: Y:\MIS_DATABASE\Library\ALTIUM_TOOL\PCB_FOOTPRINTS\Altium_Footprint_Lib.PcbLib; Height: 0.40MM; Library Path: Y:\MIS_DATABASE\Library\ALTIUM_TOOL\SCHEMATICS_PARTS\MS_DISCRETE_Library.schlib; Mfr_name: PANASONIC-ECG; Mfr_part_number: ERJ-2RKF6803X; Mistral Part No: 110011040004-R; Package: 0402; Part_type: RESISTORS\FIXED; Project: AM4515_EVM_LCD; RoHS: RoHS; Temperature: -55°C+155°C; Tolerance: 1%; Voltage: NA; Wattage: 1/10W; Weight: 0.8mg; Datasheet: Y:\MIS_DATABASE\DATASHEETS\RESISTORS\PAN-ERJSER_NOV17.PDF
R648 = RESISTOR: RES 44.2K 1/16W 1% 0402; Chkd/date: ALVY/041120; Crtd /date: ALVY/041120; Custom_Duty: 15%; Customs_HS_Code: 85332119; Distributor_name: DIGIKEY; Distributor_part_number: 541-4106-1-ND; Footprint Path: Y:\MIS_DATABASE\Library\ALTIUM_TOOL\PCB_FOOTPRINTS\Altium_Footprint_Lib.PcbLib; Height: 0.35MM; Library Path: Y:\MIS_DATABASE\Library\ALTIUM_TOOL\SCHEMATICS_PARTS\MS_DISCRETE_Library.schlib; Mfr_name: VISHAY; Mfr_part_number: CRCW040244K2FKEDC; Mistral Part No: 110010070032-R; Package: 0402; Part_type: RESISTORS\FIXED; Project: TI_J7ES_EVM_FUSION2_SER_CAP; RoHS: RoHS; Temperature: -55°C+155°C; Tolerance: 1%; Voltage: NA; Wattage: 1/16W; Weight: 0.65mg; Datasheet: Y:\MIS_DATABASE\DATASHEETS\RESISTORS\CRCW_C-SER.PDF
R649 R650 = RESISTOR: RES 0E 1/10W JUMPER 0402; Chkd/date: VASANTHA/061216; Crtd /date: NAVEED/201014; Custom_Duty: 15%; Customs_HS_Code: 85332119; Distributor_name: DIGIKEY; Distributor_part_number: P0.0JCT-ND; Footprint Path: Y:\MIS_DATABASE\Library\ALTIUM_TOOL\PCB_FOOTPRINTS\Altium_Footprint_Lib.PcbLib; Height: 0.40MM; Library Path: Y:\MIS_DATABASE\Library\ALTIUM_TOOL\SCHEMATICS_PARTS\MS_DISCRETE_Library.schlib; Mfr_name: PANASONIC-ECG; Mfr_part_number: ERJ-2GE0R00X; Mistral Part No: 110018030052-R; Package: 0402; Part_type: RESISTORS\FIXED; Project: AEGIS POM; RoHS: RoHS; Temperature: -55°C+155°C; Tolerance: NA; Voltage: NA; Wattage: 1/10W; Weight: 0.8mg; Datasheet: Y:\MIS_DATABASE\DATASHEETS\RESISTORS\PAN-ERJSER_NOV17.PDF
R661 R668 = RESISTOR: RES 10K 1/16W 5% 0402; Chkd/date: VASANTHA/061216; Crtd /date: MAZHAR/230805; Custom_Duty: 15%; Customs_HS_Code: 85332119; Distributor_name: DIGIKEY; Distributor_part_number: 311-10KJRCT-ND; Footprint Path: Y:\MIS_DATABASE\Library\ALTIUM_TOOL\PCB_FOOTPRINTS\Altium_Footprint_Lib.PcbLib; Height: 0.40MM; Library Path: Y:\MIS_DATABASE\Library\ALTIUM_TOOL\SCHEMATICS_PARTS\MS_DISCRETE_Library.schlib; Mfr_name: YAGEO AMERICA; Mfr_part_number: RC0402JR-0710KL; Mistral Part No: 110011060021-R; Package: 0402; Part_type: RESISTORS\FIXED; Project: HSE; RoHS: RoHS; Temperature: -55°C+155°C; Tolerance: 5%; Voltage: NA; Wattage: 1/16W; Weight: 0.65mg; Datasheet: Y:\MIS_DATABASE\DATASHEETS\RESISTORS\RCXXXXL-SER_MAR18.PDF
R663 = RESISTOR: RES 0.005E 1W 1% AUTO 1206 (HP); Chkd/date: MANIRAJA/280920; Crtd /date: ALVY/250920; Custom_Duty: 15%; Customs_HS_Code: 85332119; Distributor_name: DIGIKEY; Distributor_part_number: WSLP-.005CT-ND; Footprint Path: Y:\MIS_DATABASE\Library\ALTIUM_TOOL\PCB_FOOTPRINTS\Altium_Footprint_Lib.PcbLib; Height: 0.89MM; Library Path: Y:\MIS_DATABASE\Library\ALTIUM_TOOL\SCHEMATICS_PARTS\MS_DISCRETE_Library.schlib; Mfr_name: VISHAY; Mfr_part_number: WSLP12065L000FEA; Mistral Part No: 110020090011-R; Package: 1206; Part_type: RESISTORS\FIXED; Project: TI_J7ES_CP; RoHS: RoHS; Temperature: -65°C+170°C; Tolerance: 1%; Voltage: NA; Wattage: 1W; Weight: 16.2mg; Datasheet: Y:\MIS_DATABASE\DATASHEETS\RESISTORS\WSLP-SERIES.PDF
R670 = RESISTOR: RES 2.05K 1/16W 1% 0402; Chkd/date: MANIRAJA/261020; Crtd /date: MANIRAJA/261020; Custom_Duty: 15%; Customs_HS_Code: 85332119; Distributor_name: DIGIKEY; Distributor_part_number: 541-2.05KLCT-ND; Footprint Path: Y:\MIS_DATABASE\Library\ALTIUM_TOOL\PCB_FOOTPRINTS\Altium_Footprint_Lib.PcbLib; Height: 0.40MM; Library Path: Y:\MIS_DATABASE\Library\ALTIUM_TOOL\SCHEMATICS_PARTS\MS_DISCRETE_Library.schlib; Mfr_name: VISHAY; Mfr_part_number: CRCW04022K05FKED; Mistral Part No: 110020100049-R; Package: 0402; Part_type: RESISTORS\FIXED; Project: TM2_1W_SEN10RO; RoHS: RoHS; Temperature: -55°C+155°C; Tolerance: 1%; Voltage: NA; Wattage: 1/16W; Weight: 0.65mg; Datasheet: Y:\MIS_DATABASE\DATASHEETS\RESISTORS\CRCW0603.PDF
R671 = RESISTOR: RES 10E 1/16W 5% 0402; Chkd/date: JEBRAN/050815; Crtd /date: JEBRAN/050815; Custom_Duty: 15%; Customs_HS_Code: 85332119; Distributor_name: DIGIKEY; Distributor_part_number: 311-10JRCT-ND; Footprint Path: Y:\MIS_DATABASE\Library\ALTIUM_TOOL\PCB_FOOTPRINTS\Altium_Footprint_Lib.PcbLib; Height: 0.40MM; Library Path: Y:\MIS_DATABASE\Library\ALTIUM_TOOL\SCHEMATICS_PARTS\MS_DISCRETE_Library.schlib; Mfr_name: YAGEO AMERICA; Mfr_part_number: RC0402JR-0710RL; Mistral Part No: 110015080004-R; Package: 0402; Part_type: RESISTORS\FIXED; Project: PDLU; RoHS: RoHS; Temperature: -55°C+155°C; Tolerance: 5%; Voltage: NA; Wattage: 1/16W; Weight: 0.65mg; Datasheet: Y:\MIS_DATABASE\DATASHEETS\RESISTORS\RCXXXXL-SER_MAR18.PDF
TP1 TP2 TP40 TP77 TP85 = TESTPOINT: TESTPOINT 1.0MM DRILL PTH; Chkd/date: MAZHAR/271211; Crtd /date: SHREESHAIL/041005; Distributor_name: NA; Distributor_part_number: NA; Height: NA; Mfr_name: LOCAL; Mistral Part No: 130009030938; Package: THRU-HOLE; Project: HSE; Datasheet: NA
TP41 TP42 TP44 = TESTPOINT: TESTPOINT CIR 40 SMD; Chkd/date: MAZHAR/190505; Crtd /date: MAZHAR/190505; Distributor_name: NA; Distributor_part_number: NA; Footprint Path: Y:\MIS_DATABASE\Library\ALTIUM_TOOL\PCB_FOOTPRINTS\Altium_Footprint_Lib.PcbLib; Height: NA; Library Path: Y:\MIS_DATABASE\Library\ALTIUM_TOOL\SCHEMATICS_PARTS\MS_DISCRETE_Library.schlib; MECHANICAL 3D STEP FILE: NA; Mfr_name: LOCAL; Mistral Part No: 130009030933; Package: SMD; Project: RAINIER-3; RoHS: NA; Temperature: NA; Tolerance: NA; Voltage: NA; Wattage: NA; Weight: NA; Datasheet: NA
TP102 = TESTPOINT: TESTPOINT CIR 20 SMD; Chkd/date: SHREESHAIL/171006; Crtd /date: MAZHAR/171006; Custom_Duty: NA; Customs_HS_Code: NA; Distributor_name: NA; Distributor_part_number: NA; Footprint Path: Y:\MIS_DATABASE\Library\ALTIUM_TOOL\PCB_FOOTPRINTS\Altium_Footprint_Lib.PcbLib; Height: NA; Library Path: Y:\MIS_DATABASE\Library\ALTIUM_TOOL\SCHEMATICS_PARTS\MS_DISCRETE_Library.schlib; MECHANICAL 3D STEP FILE: NA; Manufacturer: LOCAL; Mfr_name: LOCAL; Mistral Part No: NA; Package: SMD; Project: BT MODULE_CSRBC04; RoHS: NA; Temperature: NA; Tolerance: NA; Voltage: NA; Wattage: NA; Weight: NA; Datasheet: NA
TP103 TP104 = TESTPOINT: TESTPOINT CIR 20 SMD; Chkd/date: SHREESHAIL/171006; Crtd /date: MAZHAR/171006; Custom_Duty: NA; Customs_HS_Code: NA; Distributor_name: NA; Distributor_part_number: NA; Footprint Path: Y:\MIS_DATABASE\Library\ALTIUM_TOOL\PCB_FOOTPRINTS\Altium_Footprint_Lib.PcbLib; Height: NA; Library Path: Y:\MIS_DATABASE\Library\ALTIUM_TOOL\SCHEMATICS_PARTS\MS_DISCRETE_Library.schlib; MECHANICAL 3D STEP FILE: NA; Mfr_name: LOCAL; Mistral Part No: NA; Package: SMD; Project: BT MODULE_CSRBC04; RoHS: NA; Temperature: NA; Tolerance: NA; Voltage: NA; Wattage: NA; Weight: NA; Datasheet: NA
U72 = TPS630701_VQFN-HR15: IC ADJ BUCK-BOOST CONVERTER WITH 3.6A SWITCH CURRENT VQFN-HR15; Chkd/date: ALVY/250122; Crtd /date: MANIRAJA/250122; Custom_Duty: 15%; Customs_HS_Code: 85423100; Distributor_name: DIGIKEY; Distributor_part_number: 296-TPS630702RNMRCT-ND; Footprint Path: Y:\MIS_DATABASE\Library\ALTIUM_TOOL\PCB_FOOTPRINTS\Altium_Footprint_Lib.PcbLib; Height: 1.00MM; Library Path: Y:\MIS_DATABASE\Library\ALTIUM_TOOL\SCHEMATICS_PARTS\MS_MISCPOWER_Library.schlib; Mfr_name: TEXAS INSTRUMENTS; Mistral Part No: 142022010015-R; Package: VQFN-HR15; Part_type: ICS\POWER\DC-DC CONVERTER; Project: AM62X_SKEVM; RoHS: RoHS; Temperature: -40°C+125°C; Tolerance: NA; Voltage: NA; Wattage: NA; Weight: 17.7mg; Datasheet: Y:\MIS_DATABASE\DATASHEETS\ICS\POWER\TPS630701X.PDF
U128 = LM5141RGET_VQFN24: IC WIDE I/P RANGE SYNCHRONOUS BUCK CONTROLLER VQFN24; Automotive Alternate_mfr_name: TEXAS INSTRUMENTS; Chkd/date: MANIRAJA/031018; Crtd /date: MANIRAJA/031018; Custom_Duty: 15%; Customs_HS_Code: 85423100; Distributor_name: DIGIKEY; Distributor_part_number: 296-44870-1-ND; Footprint Path: Y:\MIS_DATABASE\Library\ALTIUM_TOOL\PCB_FOOTPRINTS\Altium_Footprint_Lib.PcbLib; Height: 1.00MM; Library Path: Y:\MIS_DATABASE\Library\ALTIUM_TOOL\SCHEMATICS_PARTS\MS_MISCPOWER_Library.schlib; Mfr_name: TEXAS INSTRUMENTS; Mistral Part No: 142018100002-R; Package: VQFN24; Part_type: ICS\POWER\CONTROL; Project: TI_J7ES_EVM_CP; RoHS: RoHS; Temperature: -40°C+150°C; Tolerance: NA; Voltage: NA; Wattage: NA; Weight: NA; Datasheet: Y:\MIS_DATABASE\DATASHEETS\ICS\POWER\LM5141-Q1.PDF
U131 = MOSFET_CSD18501Q5A: IC MOSFET N-CHANNEL 30V 47A VSON8; Chkd/date: VASANTHA/13115; Crtd /date: VASANTHA/13115; Custom_Duty: 15%; Customs_HS_Code: 85423100; Distributor_name: DIGIKEY; Distributor_part_number: 296-27210-1-ND; Footprint Path: Y:\MIS_DATABASE\Library\ALTIUM_TOOL\PCB_FOOTPRINTS\Altium_Footprint_Lib.PcbLib; Height: 1.10MM; Library Path: Y:\MIS_DATABASE\Library\ALTIUM_TOOL\SCHEMATICS_PARTS\MS_MOSFET_Library.schlib; Mfr_name: TEXAS INSTRUMENTS; Mistral Part No: 142015110013-R; Package: SON8; Part_type: ICS\POWER\MOSFET; Project: OCTASIC_3600; RoHS: RoHS; Temperature: -55°C+150°C; Tolerance: NA; Voltage: 30V; Wattage: NA; Weight: NA; Datasheet: Y:\MIS_DATABASE\DATASHEETS\DISCRETES\TRANSISTORS_FETS\CSD17308Q3.PDF

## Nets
DGND: C292.2 C294.2 C296.2 C301.2 C303.2 C304.2 C305.2 C306.2 C307.2 C309.2 C311.2 C312.2 C314.2 C315.2 C319.1 C320.1 C321.2 C322.2 C323.2 C324.2 C325.2 C328.2 C619.1 C621.1 C623.2 C624.2 C625.1 C626.2 C627.2 C628.2 C630.2 C631.2 C632.2 C633.2 C635.2 C636.2 C641.2 C642.2 C643.2 C644.2 J21.2 J21.10 Q11.1(1S) Q11.2(2S) Q11.3(3S) R391.2 R648.2 R662.2 R666.2 R681.2 R682.2 TP1.1(TP) TP2.1(TP) TP40.1(TP) TP41.1(TP) TP42.1(TP) TP44.1(TP) TP77.1(TP) TP85.1(TP) U69.4(GND) U72.4(GND) U72.10(PGND) U72.15(VSEL) U128.3(AGND) U128.6(OSC) U128.9(PGND) U128.16(VCCX) U128.25(EP) U128.A1 U128.A2 U128.A3 U128.A4 U129.20(GND) U129.51(GND) U129.59(GND) ; also on sheet 1 2 3 4 5 6 7 8 9 10 12 13 14 16 17 18 19 20 21 22 33 34 35 36 37 38 39 40 41 42 43 44 45 46 47 48 49 50 51 52 53 54 55 56 57 58
VBUS_TYPEC1: C321.1 C641.1 C643.1 U129.13(VBUS1) ; also on sheet 12 33
VBUS_TYPEC2: C325.1 C642.1 C644.1 U129.3(VBUS2) ; also on sheet 33 52
VCC_3V3_MAIN: C619.2 C621.2 C624.1 R659.2 R663.2 R668.2 TP102.1(TP) ; also on sheet 2 13 14 33 43
VCC_3V3_MAIN_PG: R668.1 U128.21(PG) ; also on sheet 33 42
VCC_3V3_SYS: R645.1 ; also on sheet 1 2 3 6 10 14 17 18 19 20 22 33 37 38 40 41 42 45 46 48 49 50 51 52 53 54 55 56 57 58
VCC_5V0: C311.1 C313.1 C314.1 C630.1 C633.1 R387.2 R392.1 R665.1 TP103.1(TP) U72.7(VOUT) ; also on sheet 6 14 34 51 52 54
VCC_5V0_EN: R647.2 U72.14(EN)
VCC_5V0_FB: C313.2 R391.1 R392.2 U72.5(FB)
VCC_5V0_PG: R388.2 ; also on sheet 10
VCC_LM5141: C627.1 D15.2(ANODE) U128.10(VCC)
VDDA_LM5141: C625.2 U128.1(DEMB) U128.2(VDDA) U128.5(DITH) U128.19(FB)
ADCIN1: R679.2 R681.1 U129.6(ADCIN1)
ADCIN2: R678.2 R682.1 U129.10(ADCIN2)
COMP_LM5141: C632.1 R670.1 U128.20(COMP)
CS_LM5141: C634.1 R667.1 U128.18(CS)
DRAIN1: U129.8(DRAIN1_1) U129.15(DRAIN1_2) U129.19(DRAIN1_3) U129.58(DRAIN1_4)
DRAIN2: U129.7(DRAIN2_1) U129.52(DRAIN2_2) U129.56(DRAIN2_3) U129.57(DRAIN2_4)
EN_LM5141_ON: R661.1 U128.23(EN)
HB_LM5141: C629.2 D15.1(CATHODE) U128.11(HB)
HO_LM5141: R671.1 U128.13(HO)
HOL_LM5141: R671.2 U128.14(HOL) U131.4(GATE)
LDO_1V8: C303.1 U129.35(LDO_1V8)
LDO_3V3: C292.1 C319.2 R374.1 R378.1 R644.1 R646.1 R658.1 R660.1 R664.1 R678.1 R679.1 U69.8(VCC) U129.9(LDO_3V3) ; also on sheet 12
LO_LM5141: R650.1 U128.8(LO)
LOL_LM5141: R649.1 U128.7(LOL)
P2_PP_EXT_ENABLE: U129.49(GPIO17/PP_EXT2) ; also on sheet 52
PD_GPIO0: R674.2 U129.16(GPIO0)
PD_HRESET: C301.1 R662.1 U129.44(HRESET)
PD_I2C_IRQ: R645.2 R655.1 ; also on sheet 55
PD_MS_I2C1_IRQ: R660.2 U129.29(~{I2C1_IRQ})
PD_MS_I2C1_SCL: R633.1 R664.2 U129.27(I2C1_SCL)
PD_MS_I2C1_SDA: R627.1 R658.2 U129.28(I2C1_SDA)
PD_S_I2C2_IRQ: R655.2 U129.34(~{I2C2_IRQ})
PD_S_I2C2_SCL: R657.2 U129.32(I2C2_SCL)
PD_S_I2C2_SDA: R656.2 U129.33(I2C2_SDA)
PD_SPI_CLK: J21.7 R652.2 U69.6(CLK)
PD_SPI_MISO: J21.5 R644.2 R654.2 U69.2(DO(IO1))
PD_SPI_MOSI: J21.8 R653.2 U69.5(DI(IO0))
PD_SPI_SS: J21.9 R646.2 R651.2 U69.1(~{CS})
PD_VIN_3V3: C320.2 U129.5(VIN_3V3)
PORT1_15W: R386.1 ; also on sheet 12
PORT2_15W: R390.1 ; also on sheet 12
PP1_CABLE: C309.1 U129.25(PP1_CABLE)
PP2_CABLE: C631.1 R665.2 U129.46(PP2_CABLE)
RES_LM5141: C626.1 U128.24(RES)
RT_LM5141: R648.1 U128.4(RT)
SoC_I2C0_SCL_R1: R657.1 ; also on sheet 17 18 19
SoC_I2C0_SDA_R1: R656.1 ; also on sheet 17 18 19
SoC_USB0_DRVVBUS_3V3: R674.1 ; also on sheet 52
SPI_HOLDn: R374.2 U69.7(~{HOLD}(IO3))
SPI_WPn: R378.2 U69.3(~{WP}(IO2))
SS_LM5141: C628.1 U128.22(SS)
SW_LM5141: C629.1 L12.1 Q11.5(D) U128.12(SW) U131.1(S1) U131.2(S2) U131.3(S3)
TEST_POWERDOWN: R647.1 ; also on sheet 3 33
USBC_CONN1_CC1: C307.1 U129.24(C1_CC1) ; also on sheet 12
USBC_CONN1_CC2: C306.1 U129.26(C1_CC2) ; also on sheet 12
USBC_CONN2_CC1: C305.1 U129.45(C2_CC1) ; also on sheet 52
USBC_CONN2_CC2: C312.1 U129.47(C2_CC2) ; also on sheet 52
VMAIN: C294.1 C296.1 C315.1 C328.1 C623.1 C636.1 R380.1 R661.2 TP104.1(TP) U72.12(VIN) U128.15(VIN) U131.5(D1) ; also on sheet 12
VMAIN_PD: C322.1 C323.1 C324.1 U129.1(PP_HV2) U129.11(PP_HV1) ; also on sheet 12
N17824845: R654.1 U129.36(SPI_MISO/GPIO8)
N17824852: R653.1 U129.37(SPI_MOSI/GPIO9)
N17824859: R652.1 U129.38(SPI_CLK/GPIO10)
N17824866: R651.1 U129.39(~{SPI_SS}/GPIO11)
N19741013: R390.2 U129.18(GPIO2)
N20506305: L8.1 U72.11(L1)
N20506307: L8.2 U72.9(L2)
N20506359: R387.1 R388.1 U72.2(PG)
N20506388: R666.1 U72.6(FB2)
N20506392: R380.2 U72.1(PS/SYNC)
N20506511: C304.1 U72.3(VAUX)
N22682556: J21.1 R633.2
N22682559: J21.3 R627.2
N26038083: C635.1 R670.2
N26038197: Q11.4(G) R649.2 R650.2
N26038205: L12.2 R663.1 R667.2
N26038227: C634.2 R659.1 U128.17(VOUT)
N26271323: R386.2 U129.17(GPIO1)

Not connected (* = marked no-connect by the designer): J21 4* 6*; U129 21(I2C3_SCL/GPIO5)* 22(I2C3_SDA/GPIO6)* 23(~{I2C3_IRQ}/GPIO7)* 30(HPD1/GPIO3)* 31(HPD2/GPIO4)* 40(GPIO12)* 41(GPIO13)* 42(GPIO14/PWM)* 43(GPIO15/PWM)* 48(GPIO16/PP_EXT1)* 50(C1_USB_P/GPIO18)* 53(C1_USB_N/GPIO19)* 54(C2_USB_P/GPIO20)* 55(C2_USB_N/GPIO21)*

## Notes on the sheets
sheet 31
- USB TYPE-C POWER
- TYPE-C DUAL PD CONTROLLER
- BP_NoWait
  Safe Configuration
- I2C Slave
   Address
- Port1
- Port2
- I2C2(Default)
- 0x38
- 0x3F
- SPI EEPROM & PROGRAMMING HEADER
- I2C1
- 0x20
- 0x24
sheet 32
- PERIPHERAL POWER SUPPLY - 1
- VinMin = 4.5V
  VinMax = 15V
  Vout = 5V @ 2A
- 5V, 2.0 AMPS SUPPLY
- SILK SCREEN : VCC_5V0
- GND TEST POINTS
- PERIPHERAL POWER SUPPLY -  2
- 3.3V, 10.0 AMPS SUPPLY
- VinMin = 4.5V
  VinMax = 15V
  Vout = 3.3V @ 10A
- @@ ALWAYS ON
- KELVIN ROUTING
- PCB Note: Short LM5141_AGND and DGND at single point
